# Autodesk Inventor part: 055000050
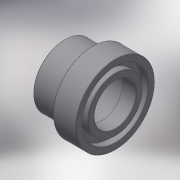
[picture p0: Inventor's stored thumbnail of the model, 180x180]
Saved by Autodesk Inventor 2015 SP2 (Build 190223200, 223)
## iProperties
Created: 2017-10
Part Number: 055000050
Material: Generic
Description: PLASSON FLANGE AD.+O-RING-CE 50
Document SubType Name: Modeling
Designer: KIM
Density: 1 g/cm^3
Appearance: Default
Author: KIM
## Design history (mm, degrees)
derived "055000.ipt"
feature "Solid1::055000.ipt"
tag "TaggingFeature1"
body "Solid1"
other parameters: "d0" = 39, "d1" = 61, "d3" = 45, "d4" = 13, "d5" = 31, "d6" = 73, "d8" = 3.9, "d11" = 0.5, "d12" = 3.9, "d15" = 4.2, "E_" = 61, "E_1" = 73, "l_" = 31, "B_" = 13, "H_" = 39, "d14" = 14
